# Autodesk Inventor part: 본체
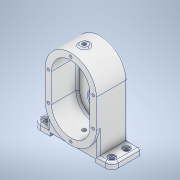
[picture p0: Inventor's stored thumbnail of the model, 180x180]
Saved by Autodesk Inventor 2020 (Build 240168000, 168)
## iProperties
Created: 2021-05
Part Number: 본체
Material: 알루미늄 6061
Document SubType Name: Modeling
Designer: Owner
Density: 2.7 g/cm^3
Appearance: 알루미늄 - 평지
Mass: 752.167 g
Surface Area: 589.363 cm^2
Volume: 278.58 cm^3
Author: Owner
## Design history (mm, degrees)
sketch "스케치2"
  geometry: L1 (0, 17.5)-(0, -17.5); L2 (40, -22.5)-(40, 22.5); L3 (-40, 22.5)-(-40, -22.5); A1 r 40 centre (0, -22.5) between (-40, -22.5) and (40, -22.5); A2 r 40 centre (0, 22.5) between (40, 22.5) and (-40, 22.5); 2 further points
  constraints: 8 end point, 6 point on circle, 4 tangent, 2 centre point, 2 point on line, 1 coincident, 1 midpoint, 1 parallel, 1 vertical
  dimensions: "d7" = 80 diameter of A2; "d48" = 45 distance of A1.centre A2.centre
extrude "돌출1" new body sketch "스케치2" distance "d8" = 49; taper "d9" = 0 deg
sketch "스케치3"
  geometry: L1 (-40, 22.5)-(-40, -22.5) reference; L2 (-40, 22.5)-(-40, -22.5) reference; L3 (40, -22.5)-(40, 22.5) reference; L4 (0, 7.5)-(0, -7.5); L5 (30, -22.5)-(30, 22.5); L6 (-30, 22.5)-(-30, -22.5); A1 r 40 centre (0, 22.5) between (40, 22.5) and (-40, 22.5) reference; A2 r 40 centre (0, -22.5) between (-40, -22.5) and (40, -22.5) reference; A3 r 40 centre (0, 22.5) between (40, 22.5) and (-40, 22.5) reference; A4 r 30 centre (0, -22.5) between (-30, -22.5) and (30, -22.5); A5 r 30 centre (0, 22.5) between (30, 22.5) and (-30, 22.5); 2 further points
  constraints: 8 end point, 6 point on circle, 4 tangent, 2 centre point, 2 point on line, 1 coincident, 1 midpoint, 1 parallel, 1 vertical
  dimensions: "d11" = 60 diameter of A5; "d47" = 45 distance of A4.centre A5.centre
extrude "돌출2" cut sketch "스케치3" distance "d12" = 41; taper "d13" = 0 deg
sketch "스케치4"
  geometry: L1 (0, -22.5)-(0, -69.5); L2 (-61, -69.5)-(-61, -59.5); L3 (-61, -59.5)-(-40, -59.5); L4 (-40, -59.5)-(-40, -22.5); L5 (40, -59.5)-(40, -22.5); L6 (61, -59.5)-(40, -59.5); L7 (61, -69.5)-(61, -59.5); L8 (-35, -69.5)-(35, -69.5); L9 (-61, -69.5)-(-35, -69.5); L10 (61, -69.5)-(35, -69.5); L11 (-35, -69.5)-(-35, -64.5); L12 (-35, -64.5)-(35, -64.5); L13 (35, -69.5)-(35, -64.5); A1 r 40 centre (0, -22.5) between (-40, -22.5) and (40, -22.5) reference; 1 further point
  constraints: 26 end point, 3 perpendicular, 3 vertical, 2 symmetric about line, 1 collinear, 1 horizontal, 1 midpoint
  dimensions: "d14" = 47 distance of L1.end L1.start; "d15" = 122 distance of L2.start L7.start; "d16" = 10 distance of L2.start L2.end; "d17" = 21 distance of L2.end L3.end; "d18" = 70 distance of L8.start L8.end; "d19" = 5 distance of L8.start L11.end
extrude "돌출3" join sketch "스케치4" distance "d20" = 49; taper "d21" = 0 deg
sketch "스케치5"
  geometry: L1 (0, 22.5)-(0, -22.5); C1 r 14 at (0, -22.5); C2 r 14 at (0, 22.5); 2 further points
  constraints: 3 coincident, 2 centre point, 2 end point, 1 midpoint, 1 point on line, 1 vertical
  dimensions: "d22" = 45 distance of L1.start L1.end; "d24" = 28 diameter of C1; "d25" = 28 diameter of C2
extrude "돌출4" cut sketch "스케치5" distance "d26" = 8; taper "d27" = 0 deg
sketch "스케치6"
  geometry: L1 (0, 48.5)-(0, -48.5); L2 (-26, 22.5)-(-26, -22.5); L3 (26, -22.5)-(26, 22.5); A1 r 26 centre (0, 22.5) between (26, 22.5) and (-26, 22.5); A2 r 26 centre (0, -22.5) between (-26, -22.5) and (26, -22.5); 2 further points
  constraints: 8 end point, 6 point on circle, 4 tangent, 2 centre point, 2 point on line, 1 coincident, 1 midpoint, 1 parallel, 1 vertical
  dimensions: "d28" = 52 distance between parallel lines of L2 L3; "d29" = 45 distance of A2.centre A1.centre
extrude "돌출5" join sketch "스케치6" distance "d30" = 8; taper "d31" = 0 deg
sketch "스케치7"
  geometry: L1 (0, 0)-(0, -45); C1 r 11 at (0, 0); C2 r 10 at (0, -45); 2 further points
  constraints: 3 coincident, 2 centre point, 2 end point, 1 midpoint, 1 vertical
  dimensions: "d35" = 45 distance of L1.start L1.end; "d36" = 22 diameter of C1; "d37" = 20 diameter of C2
extrude "돌출6" cut sketch "스케치7" distance "d38" = 4; taper "d39" = 0 deg
sketch "스케치8"
  geometry: L1 (0, 0)-(0, -45); C1 r 14 at (0, 0); 2 further points
  constraints: 2 coincident, 2 end point, 1 centre point, 1 midpoint, 1 vertical
  dimensions: "d40" = 45 distance of L1.start L1.end; "d41" = 28 diameter of C1
extrude "돌출7" cut sketch "스케치8" extent not by distance; stored distance "d42" = 3; taper "d43" = 0 deg
sketch "스케치9"
  geometry: L1 (-35, 22.5)-(-35, -22.5); L2 (35, 22.5)-(35, -22.5); L3 (0, 22.5)-(0, 12.5); L4 (0, -12.5)-(0, -22.5); A1 r 35 centre (0, 22.5) between (35, 22.5) and (-35, 22.5); A2 r 35 centre (0, -22.5) between (-35, -22.5) and (35, -22.5); 8 further points
  constraints: 8 end point, 8 point on circle, 7 coincident, 2 centre point, 2 vertical, 1 tangent
  dimensions: "d44" = 45 distance of L3.start L4.end
hole "구멍1" sketch "스케치9" at (0, 57.5), (-35, 22.5), (35, 22.5), (0, -57.5), (-35, -22.5), (35, -22.5) diameter "d49" = 4; stored, may be unused: countersink angle "d53" = 90 deg, drill point angle "d55" = 118 deg; dims "d50" = 6, "d51" = 4, "d52" = 2, "d54" = 10
sketch "스케치11" dims "d59" = 40
  geometry: L1 (0, 22.5)-(0, -7.5); L2 (0, -7.5)-(-26, -7.5); L3 (0, -7.5)-(26, -7.5); L4 (-26, 22.5)-(-26, -22.5) reference; L5 (26, -22.5)-(26, 22.5) reference; A1 r 26 centre (0, -22.5) between (-26, -22.5) and (26, -22.5) reference; 6 further points
  constraints: 6 end point, 2 coincident, 2 horizontal, 1 vertical alignment, 6 other
  dimensions: "d58" = 30 distance of L1.start L1.end; "d62" = 360 deg dimension on L1.start point (0, 42.5) (derived)
hole "구멍2" sketch "스케치11" diameter "d64" = 4; stored, may be unused: countersink angle "d68" = 90 deg, drill point angle "d70" = 118 deg; dims "d65" = 6, "d66" = 4, "d67" = 2, "d69" = 10
extrude "돌출8" join sketch "스케치11" distance "d71" = 3; taper "d72" = 0 deg
sketch "스케치12"
  geometry: 1 further point
node "작업 평면3"
sketch "스케치13"
  geometry: L1 (0, -22.5)-(0, -69.5); L2 (-61, -69.5)-(-61, -59.5); L3 (-61, -59.5)-(-40, -59.5); L4 (-40, -59.5)-(-40, -22.5); L5 (40, -59.5)-(40, -22.5); L6 (61, -59.5)-(40, -59.5); L7 (61, -69.5)-(61, -59.5); L8 (-35, -69.5)-(35, -69.5); L9 (-61, -69.5)-(-35, -69.5); L10 (61, -69.5)-(35, -69.5); L11 (-35, -69.5)-(-35, -64.5); L12 (-35, -64.5)-(35, -64.5); L13 (35, -69.5)-(35, -64.5); A1 r 40 centre (0, -22.5) between (-40, -22.5) and (40, -22.5); 2 further points
  constraints: 26 end point, 3 perpendicular, 3 vertical, 2 point on circle, 2 symmetric about line, 1 centre point, 1 collinear, 1 horizontal, 1 midpoint
  dimensions: "d74" = 47 distance of L1.end L1.start; "d75" = 122 distance of L2.start L7.start; "d76" = 10 distance of L2.start L2.end; "d77" = 21 distance of L2.end L3.end; "d78" = 70 distance of L8.start L8.end; "d79" = 5 distance of L8.start L11.end
extrude "돌출9" cut sketch "스케치13" distance "d80" = 49; taper "d81" = 0 deg
node "작업 평면4"
sketch "스케치15"
  geometry: 1 further point
fillet "모깎기1" dims "d91" = 10
sketch "스케치17"
  geometry: C1 r 5.5 at (-11, 33); C2 r 5.5 at (-11, 10); C3 r 5.5 at (91, 33); C4 r 5.5 at (91, 10); C5 r 3.3 at (91, 33); C6 r 3.3 at (91, 10); C7 r 3.3 at (-11, 33); C8 r 3.3 at (-11, 10); A1 r 10 centre (-11, 10) between (-21, 10) and (-11, 0) reference; A2 r 10 centre (-11, 33) between (-11, 43) and (-21, 33) reference; A3 r 10 centre (91, 33) between (101, 33) and (91, 43) reference; A4 r 10 centre (91, 10) between (91, 0) and (101, 10) reference; 5 further points
  constraints: 12 coincident, 8 centre point
  dimensions: "d92" = 11 diameter of C1; "d93" = 11 diameter of C2; "d94" = 11 diameter of C3; "d95" = 11 diameter of C4; "d96" = 6.6 diameter of C5; "d97" = 6.6 diameter of C6; "d98" = 6.6 diameter of C7; "d99" = 6.6 diameter of C8
extrude "돌출11" cut sketch "스케치17" distance "d100" = 2; taper "d101" = 0 deg
extrude "돌출12" cut sketch "스케치17" extent not by distance; stored distance "d102" = 0; taper "d103" = 0 deg
node "작업 평면5"
sketch "스케치18"
  geometry: L1 (-30, 49)-(30, 49) reference; L2 (0, 49)-(0, 28); C1 r 6 at (0, 28); 1 further point
  constraints: 2 end point, 1 centre point, 1 coincident, 1 midpoint
  dimensions: "d105" = 21 distance of L2.start L2.end; "d106" = 12 diameter of C1
extrude "돌출13" join sketch "스케치18" stored distance "d107" = 3; taper "d108" = 0 deg
sketch "스케치19"
  geometry: C1 r 6 at (0, 0) reference; 2 further points
  constraints: 1 coincident
hole "구멍3" sketch "스케치19" at (0, 0) diameter "d109" = 6; stored, may be unused: countersink angle "d113" = 90 deg, drill point angle "d115" = 118 deg; dims "d110" = 6, "d111" = 4, "d112" = 2, "d114" = 6
sketch "스케치21"
  geometry: C1 r 3 at (35, -18) reference; C2 r 3 at (35, -18) reference; C3 r 6 at (35, -18); 1 further point
  constraints: 1 centre point, 1 coincident
  dimensions: "d119" = 12 diameter of C3
extrude "돌출14" cut sketch "스케치21" distance "d120" = 1; taper "d121" = 0 deg
fillet "모깎기2" dims "d122" = 0.3
fillet "모깎기3" dims "d123" = 3
chamfer "모따기1" distance "d124" = 1; stored, may be unused: second distance "d125" = 2, angle "d126" = 45 deg
fillet "모깎기4" dims "d127" = 3
fillet "모깎기5" dims "d128" = 3
sketch "스케치22"
  geometry: L1 (-58, -69.5)-(-35, -69.5) reference; L2 (0, -69.5)-(0, -57.5); L3 (59, -30)-(109, -30); L4 (0, -57.5)-(30, -57.5); L5 (0, -57.5)-(-30, -57.5); L6 (30, -59.5)-(0, -59.5); L7 (0, -59.5)-(-30, -59.5); L8 (-30, -59.5)-(30, -59.5); C1 r 2 at (0, -57.5) reference; 1 further point
  constraints: 14 end point, 4 horizontal, 1 collinear, 1 other
  dimensions: "d130" = 50 distance of L3.start L3.end; "d134" = 2 distance between parallel lines of L4 L6
extrude "돌출15" join sketch "스케치22" distance "d135" = 0.5; taper "d136" = 0 deg
node "솔리드1"
node "투영된 루프1"
feature "A9D066F2-1C7D-4E18-AEED-F7BC21143FA4" dims "d49" = 4, "d50" = 6, "d51" = 4, "d52" = 2, "d53" = 90 deg, "d54" = 10, "d55" = 118 deg
other parameters: "d82" = -3, "d104" = 62.5
